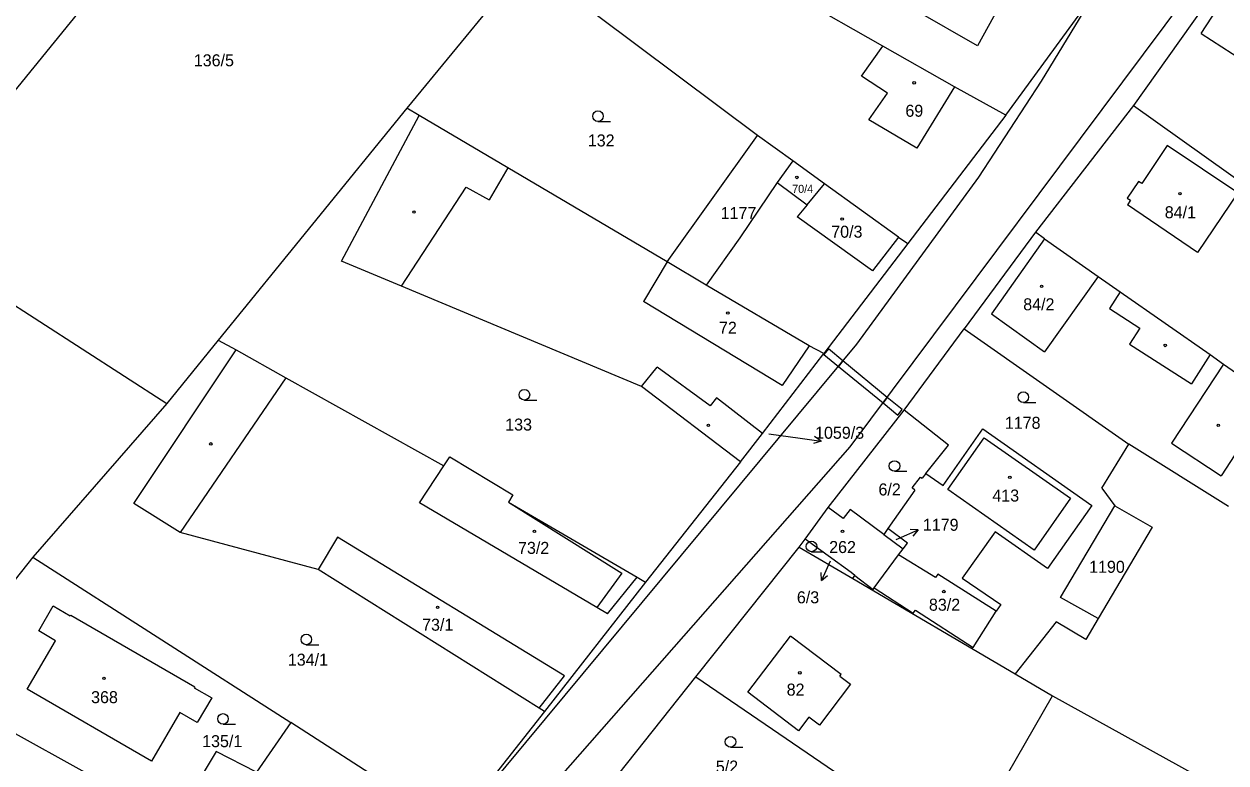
# Model space of a CAD drawing. Extents: x -694609 to -690140, y -1033292 to -1029794.
# Drawn here: x -692609.2 to -692438.9, y -1031810 to -1031705.3 of the extents above; entities that cross this region are included whole.
import ezdxf
from ezdxf.enums import TextEntityAlignment as Align

# ---------------------------------------------------------------- set-up
doc = ezdxf.new("R2010")
doc.units = 0
doc.header["$LTSCALE"] = 0.68
for name, color, linetype, lineweight in [('1', 7, 'Continuous', 25), ('13', 7, 'Continuous', 13), ('3', 7, 'Continuous', 25), ('4', 7, 'Continuous', 13), ('5', 7, 'Continuous', 25), ('7', 7, 'Continuous', 13)]:
    doc.layers.add(name, color=color, linetype=linetype, lineweight=lineweight)
doc.layers.add('2', color=7, linetype='Continuous')

msp = doc.modelspace()

# ---------------------------------------------------------------- linework, layer by layer
at = {"layer": '1'}
for p, q in [((-692593.96, -1031694.43), (-692626.76, -1031734.71)), ((-692467.92, -1031697.25), (-692474.09, -1031708.43)), ((-692487.5, -1031708.49), (-692503.62, -1031699.3)), ((-692492.12, -1031765.22), (-692442.05, -1031698.19)), ((-692470.09, -1031718.27), (-692457.55, -1031701.11)), ((-692465.03, -1031713.42), (-692457.55, -1031701.11)), ((-692505.25, -1031721.15), (-692527.93, -1031704.17)), ((-692474.09, -1031708.43), (-692482.82, -1031703.44)), ((-692477.36, -1031714.26), (-692487.5, -1031708.49)), ((-692470.09, -1031718.27), (-692477.36, -1031714.26)), ((-692473.9, -1031727.05), (-692465.03, -1031713.42)), ((-692554.95, -1031717.27), (-692581.65, -1031750.09)), ((-692564.18, -1031738.94), (-692553.18, -1031718.31)), ((-692553.18, -1031718.31), (-692554.95, -1031717.27)), ((-692540.63, -1031725.72), (-692553.18, -1031718.31)), ((-692470.09, -1031718.27), (-692483.96, -1031736.43)), ((-692451.98, -1031716.89), (-692425.76, -1031735.6)), ((-692518.08, -1031739.03), (-692505.25, -1031721.15)), ((-692500.28, -1031724.73), (-692505.25, -1031721.15)), ((-692495.76, -1031727.98), (-692500.28, -1031724.73)), ((-692518.08, -1031739.03), (-692540.63, -1031725.72)), ((-692502.48, -1031727.77), (-692507.78, -1031735.6)), ((-692498.22, -1031730.94), (-692495.76, -1031727.98)), ((-692485.27, -1031735.52), (-692495.76, -1031727.98)), ((-692491.21, -1031750.69), (-692473.9, -1031727.05)), ((-692626.76, -1031734.71), (-692588.96, -1031759.08)), ((-692465.89, -1031734.84), (-692475.97, -1031748.51)), ((-692464.62, -1031735.78), (-692465.89, -1031734.84)), ((-692507.78, -1031735.6), (-692512.52, -1031742.31)), ((-692483.96, -1031736.43), (-692495.85, -1031752)), ((-692485.27, -1031735.52), (-692483.96, -1031736.43)), ((-692464.62, -1031735.78), (-692456.99, -1031741.08)), ((-692555.71, -1031742.48), (-692564.18, -1031738.94)), ((-692512.52, -1031742.31), (-692518.08, -1031739.03)), ((-692456.99, -1031741.08), (-692453.87, -1031743.26)), ((-692521.7, -1031756.69), (-692555.71, -1031742.48)), ((-692497.95, -1031750.91), (-692512.52, -1031742.31)), ((-692453.87, -1031743.26), (-692441.12, -1031752.15)), ((-692484.5, -1031760.01), (-692475.97, -1031748.51)), ((-692475.97, -1031748.51), (-692452.67, -1031764.84)), ((-692581.65, -1031750.09), (-692588.96, -1031759.08)), ((-692581.65, -1031750.09), (-692579.14, -1031751.46)), ((-692559.98, -1031833.38), (-692491.21, -1031750.69)), ((-692504.56, -1031763.33), (-692495.85, -1031752)), ((-692495.85, -1031752), (-692497.95, -1031750.91)), ((-692441.12, -1031752.15), (-692439.26, -1031753.5)), ((-692439.26, -1031753.5), (-692432.4, -1031758.29)), ((-692572.07, -1031755.43), (-692549.71, -1031767.89)), ((-692507.66, -1031767.36), (-692521.7, -1031756.69)), ((-692588.96, -1031759.08), (-692607.91, -1031780.86)), ((-692495.25, -1031773.83), (-692484.5, -1031760.01)), ((-692478.23, -1031765), (-692484.5, -1031760.01)), ((-692507.66, -1031767.36), (-692504.56, -1031763.33)), ((-692478.94, -1031770.67), (-692473.35, -1031762.69)), ((-692551.82, -1031833.09), (-692492.12, -1031765.22)), ((-692481.4, -1031768.97), (-692478.23, -1031765)), ((-692456.48, -1031771.07), (-692452.67, -1031764.84)), ((-692438.54, -1031773.68), (-692452.67, -1031764.84)), ((-692549.71, -1031767.89), (-692548.84, -1031766.64)), ((-692548.84, -1031766.64), (-692539.91, -1031772)), ((-692507.66, -1031767.36), (-692521.11, -1031784.39)), ((-692553.16, -1031773.15), (-692549.71, -1031767.89)), ((-692481.4, -1031768.97), (-692481.95, -1031769.67)), ((-692481.4, -1031768.97), (-692478.94, -1031770.67)), ((-692483.36, -1031771), (-692482.17, -1031769.51)), ((-692482.96, -1031771.33), (-692483.36, -1031771)), ((-692482.17, -1031769.51), (-692481.95, -1031769.67)), ((-692456.48, -1031771.07), (-692454.65, -1031773.57)), ((-692539.91, -1031772), (-692540.55, -1031773.03)), ((-692482.96, -1031771.33), (-692486.8, -1031776.8)), ((-692587.05, -1031777.35), (-692593.64, -1031773.23)), ((-692528.04, -1031787.96), (-692553.16, -1031773.15)), ((-692540.55, -1031773.03), (-692522.33, -1031783.67)), ((-692498.49, -1031778.28), (-692495.25, -1031773.83)), ((-692493.12, -1031775.38), (-692495.25, -1031773.83)), ((-692492.13, -1031774.07), (-692493.12, -1031775.38)), ((-692487.38, -1031777.62), (-692492.13, -1031774.07)), ((-692462.36, -1031786.55), (-692454.65, -1031773.57)), ((-692454.65, -1031773.57), (-692449.36, -1031776.6)), ((-692567.5, -1031782.59), (-692587.05, -1031777.35)), ((-692486.8, -1031776.8), (-692487.38, -1031777.62)), ((-692487.38, -1031777.62), (-692484.64, -1031779.66)), ((-692484.01, -1031778.88), (-692486.8, -1031776.8)), ((-692471.61, -1031777.23), (-692476.25, -1031783.83)), ((-692464.17, -1031782.44), (-692471.61, -1031777.23)), ((-692449.36, -1031776.6), (-692456.99, -1031789.54)), ((-692514, -1031797.79), (-692499.34, -1031779.43)), ((-692499.34, -1031779.43), (-692498.49, -1031778.28)), ((-692499.34, -1031779.43), (-692491.77, -1031783.87)), ((-692491.98, -1031783.02), (-692498.49, -1031778.28)), ((-692484.64, -1031779.66), (-692484.01, -1031778.88)), ((-692607.91, -1031780.86), (-692622.58, -1031799.12)), ((-692607.91, -1031780.86), (-692571.38, -1031804.26)), ((-692488.72, -1031785.18), (-692485.27, -1031780.51)), ((-692485.27, -1031780.51), (-692484.64, -1031779.66)), ((-692480.04, -1031783.73), (-692485.27, -1031780.51)), ((-692536.22, -1031802.22), (-692567.5, -1031782.59)), ((-692491.46, -1031783.42), (-692491.98, -1031783.02)), ((-692526.5, -1031788.86), (-692522.33, -1031783.67)), ((-692522.33, -1031783.67), (-692521.11, -1031784.39)), ((-692491.77, -1031783.87), (-692491.46, -1031783.42)), ((-692491.77, -1031783.87), (-692468.74, -1031797.35)), ((-692491.46, -1031783.42), (-692488.89, -1031785.4)), ((-692479.71, -1031783.27), (-692480.04, -1031783.73)), ((-692471.46, -1031788.47), (-692479.71, -1031783.27)), ((-692476.25, -1031783.83), (-692470.78, -1031787.52)), ((-692488.89, -1031785.4), (-692488.72, -1031785.18)), ((-692488.72, -1031785.18), (-692483.21, -1031788.75)), ((-692607.08, -1031791.29), (-692605.05, -1031787.72)), ((-692605.05, -1031787.72), (-692602.65, -1031789.15)), ((-692526.5, -1031788.86), (-692528.04, -1031787.96)), ((-692470.78, -1031787.52), (-692471.46, -1031788.47)), ((-692456.99, -1031789.54), (-692462.36, -1031786.55)), ((-692602.65, -1031789.15), (-692602.56, -1031789.04)), ((-692602.56, -1031789.04), (-692585, -1031799.21)), ((-692483.21, -1031788.75), (-692482.87, -1031788.36)), ((-692482.87, -1031788.36), (-692474.72, -1031793.62)), ((-692474.72, -1031793.62), (-692471.46, -1031788.47)), ((-692456.99, -1031789.54), (-692458.73, -1031792.5)), ((-692604.74, -1031792.69), (-692607.08, -1031791.29)), ((-692462.95, -1031790.01), (-692468.74, -1031797.35)), ((-692458.73, -1031792.5), (-692462.95, -1031790.01)), ((-692608.73, -1031799.52), (-692604.74, -1031792.69)), ((-692524.91, -1031811.52), (-692514, -1031797.79)), ((-692514, -1031797.79), (-692494.36, -1031811.2)), ((-692468.74, -1031797.35), (-692463.48, -1031800.46)), ((-692598.83, -1031812.27), (-692622.58, -1031799.12)), ((-692591.13, -1031809.74), (-692608.73, -1031799.52)), ((-692585, -1031799.21), (-692585.07, -1031799.34)), ((-692585.07, -1031799.34), (-692582.59, -1031800.76)), ((-692582.59, -1031800.76), (-692584.63, -1031804.25)), ((-692477.55, -1031824.98), (-692463.48, -1031800.46)), ((-692463.48, -1031800.46), (-692416.83, -1031826.23)), ((-692587.11, -1031802.82), (-692591.13, -1031809.74)), ((-692584.63, -1031804.25), (-692587.11, -1031802.82)), ((-692535.46, -1031802.7), (-692548.33, -1031819.07)), ((-692548.33, -1031819.07), (-692571.38, -1031804.26)), ((-692581.95, -1031808.36), (-692585.34, -1031814))]:
    msp.add_line(p, q, dxfattribs=at)
for points in [[(-692533.41, -1031691.28), (-692535.83, -1031694), (-692554.95, -1031717.27)], [(-692440.5, -1031700.65), (-692451.98, -1031716.89), (-692465.89, -1031734.84)], [(-692500.28, -1031724.73), (-692502.48, -1031727.77), (-692498.22, -1031730.94)], [(-692593.64, -1031773.23), (-692579.14, -1031751.46), (-692572.07, -1031755.43)], [(-692473.35, -1031762.69), (-692457.92, -1031773.51), (-692464.17, -1031782.44)], [(-692521.11, -1031784.39), (-692535.46, -1031802.7), (-692536.22, -1031802.22)], [(-692571.38, -1031804.26), (-692576.24, -1031811.29), (-692581.95, -1031808.36)]]:
    msp.add_lwpolyline(points, dxfattribs=at)
at = {"layer": '13'}
for points in [[(-692495.85, -1031752.15), (-692493.81, -1031753.82), (-692493.17, -1031753.05), (-692495.23, -1031751.36)], [(-692493.17, -1031753.05), (-692493.81, -1031753.82), (-692487.48, -1031759.01), (-692486.88, -1031758.21)], [(-692487.48, -1031759.01), (-692485.4, -1031760.72), (-692484.77, -1031759.95), (-692486.88, -1031758.21)]]:
    msp.add_lwpolyline(points, close=True, dxfattribs=at)
at = {"layer": '3'}
for p, q in [((-692527.863, -1031719.14), (-692526.113, -1031719.14)), ((-692538.293, -1031758.59), (-692536.543, -1031758.59)), ((-692467.603, -1031758.93), (-692465.853, -1031758.93)), ((-692485.853, -1031768.68), (-692484.103, -1031768.68)), ((-692497.613, -1031780.07), (-692495.863, -1031780.07)), ((-692569.183, -1031793.24), (-692567.433, -1031793.24)), ((-692580.983, -1031804.49), (-692579.233, -1031804.49)), ((-692509.093, -1031807.74), (-692507.343, -1031807.74))]:
    msp.add_line(p, q, dxfattribs=at)
for centre in [(-692527.8629, -1031718.3898), (-692538.2929, -1031757.8398), (-692467.6029, -1031758.1798), (-692485.8529, -1031767.9298), (-692497.6129, -1031779.3198), (-692569.1829, -1031792.4898), (-692580.9829, -1031803.7398), (-692509.0929, -1031806.9898)]:
    msp.add_circle(centre, 0.75, dxfattribs=at)
at = {"layer": '4'}
for p, q in [((-692442.42, -1031706.71), (-692439.38, -1031702.08)), ((-692442.42, -1031706.71), (-692423.59, -1031718.8)), ((-692477.36, -1031714.26), (-692482.7, -1031722.91)), ((-692482.7, -1031722.91), (-692489.51, -1031718.93)), ((-692447.21, -1031722.56), (-692450.83, -1031727.94)), ((-692437.23, -1031729.27), (-692447.21, -1031722.56)), ((-692540.63, -1031725.72), (-692543.26, -1031730.22)), ((-692450.83, -1031727.94), (-692451.28, -1031727.63)), ((-692437.23, -1031729.27), (-692442.92, -1031737.68)), ((-692498.22, -1031730.94), (-692499.66, -1031732.67)), ((-692452.42, -1031730.3), (-692452.86, -1031730.95)), ((-692442.92, -1031737.68), (-692452.86, -1031730.95)), ((-692488.96, -1031740.31), (-692499.66, -1031732.67)), ((-692485.27, -1031735.52), (-692488.96, -1031740.31)), ((-692464.62, -1031735.78), (-692472.11, -1031746.4)), ((-692518.08, -1031739.03), (-692521.44, -1031744.65)), ((-692456.99, -1031741.08), (-692464.61, -1031751.75)), ((-692501.76, -1031756.52), (-692521.44, -1031744.65)), ((-692472.11, -1031746.4), (-692464.61, -1031751.75)), ((-692452.56, -1031750.68), (-692443.78, -1031756.31)), ((-692497.95, -1031750.91), (-692501.76, -1031756.52)), ((-692441.12, -1031752.15), (-692443.78, -1031756.31)), ((-692521.7, -1031756.69), (-692519.46, -1031753.95)), ((-692511.99, -1031759.39), (-692519.46, -1031753.95)), ((-692439.26, -1031753.5), (-692446.61, -1031764.71)), ((-692572.07, -1031755.43), (-692587.05, -1031777.35)), ((-692511.07, -1031758.3), (-692511.99, -1031759.39)), ((-692504.56, -1031763.33), (-692511.07, -1031758.3)), ((-692432.4, -1031758.29), (-692439.6, -1031769.3)), ((-692478.31, -1031771.26), (-692473.17, -1031763.93)), ((-692473.17, -1031763.93), (-692460.94, -1031772.48)), ((-692446.61, -1031764.71), (-692439.6, -1031769.3)), ((-692466.08, -1031779.84), (-692478.31, -1031771.26)), ((-692460.94, -1031772.48), (-692466.08, -1031779.84)), ((-692540.55, -1031773.03), (-692524.48, -1031783.12)), ((-692524.48, -1031783.12), (-692528.04, -1031787.96)), ((-692506.64, -1031799.98), (-692500.61, -1031792.01)), ((-692536.22, -1031802.22), (-692532.61, -1031797.65)), ((-692493.61, -1031797.67), (-692492.1, -1031798.82)), ((-692499.46, -1031805.41), (-692506.64, -1031799.98)), ((-692492.1, -1031798.82), (-692496.5, -1031804.64)), ((-692498.01, -1031803.5), (-692499.46, -1031805.41)), ((-692496.5, -1031804.64), (-692498.01, -1031803.5))]:
    msp.add_line(p, q, dxfattribs=at)
for points in [[(-692489.51, -1031718.93), (-692486.86, -1031715.15), (-692490.51, -1031712.73), (-692487.5, -1031708.49)], [(-692555.71, -1031742.48), (-692546.55, -1031728.46), (-692543.26, -1031730.22)], [(-692451.28, -1031727.63), (-692452.88, -1031729.99), (-692452.42, -1031730.3)], [(-692453.87, -1031743.26), (-692455.4, -1031745.64), (-692451.1, -1031748.4), (-692452.56, -1031750.68)], [(-692532.61, -1031797.65), (-692564.77, -1031778.02), (-692567.5, -1031782.59)], [(-692493.61, -1031797.67), (-692493.43, -1031797.44), (-692500.61, -1031792.01)]]:
    msp.add_lwpolyline(points, dxfattribs=at)
at = {"layer": '5'}
for centre in [(-692483.0668, -1031713.6692), (-692499.6868, -1031727.0692), (-692445.4168, -1031729.3792), (-692553.9368, -1031731.9692), (-692493.2768, -1031732.9592), (-692465.0168, -1031742.4792), (-692509.4668, -1031746.2692), (-692447.5068, -1031750.8592), (-692512.2268, -1031762.1692), (-692439.9868, -1031762.1792), (-692582.7168, -1031764.7992), (-692469.5168, -1031769.5292), (-692536.8668, -1031777.1792), (-692493.2268, -1031777.1892), (-692478.8668, -1031785.7092), (-692550.5768, -1031787.9492), (-692597.8568, -1031798.0092), (-692499.2668, -1031797.2192)]:
    msp.add_circle(centre, 0.175, dxfattribs=at)
at = {"layer": '7'}
for p, q in [((-692496.268, -1031764.398), (-692497.19, -1031763.762)), ((-692482.528, -1031776.979), (-692483.647, -1031776.929)), ((-692496.211, -1031784.132), (-692495.346, -1031783.42))]:
    msp.add_line(p, q, dxfattribs=at)
for points in [[(-692503.65, -1031763.36), (-692499.24, -1031763.98), (-692496.268, -1031764.398), (-692497.33, -1031764.754)], [(-692485.6, -1031778.35), (-692485.27, -1031778.2), (-692482.528, -1031776.979), (-692483.24, -1031777.844)], [(-692494.99, -1031781.39), (-692496.211, -1031784.132), (-692496.261, -1031783.013)]]:
    msp.add_lwpolyline(points, dxfattribs=at)

# ---------------------------------------------------------------- texts
at = {"layer": '2'}
for s, height, p in [('136/5', 1.7, (-692582.28, -1031711.335)), ('69', 1.7, (-692483.049, -1031718.475)), ('132', 1.7, (-692527.409, -1031722.685)), ('70/4', 1.139, (-692498.869, -1031729.254)), ('1177', 1.7, (-692507.96, -1031732.965)), ('84/1', 1.7, (-692445.359, -1031732.845)), ('70/3', 1.7, (-692492.609, -1031735.605)), ('84/2', 1.7, (-692465.409, -1031745.885)), ('72', 1.7, (-692509.459, -1031749.205)), ('133', 1.7, (-692539.109, -1031762.915)), ('1178', 1.7, (-692467.7, -1031762.665)), ('6/2', 1.7, (-692486.55, -1031772.095)), ('413', 1.7, (-692470.099, -1031772.965)), ('73/2', 1.7, (-692536.979, -1031780.375)), ('262', 1.7, (-692493.219, -1031780.255)), ('1190', 1.7, (-692455.76, -1031783.055)), ('83/2', 1.7, (-692478.769, -1031788.425)), ('73/1', 1.7, (-692550.569, -1031791.255)), ('134/1', 1.7, (-692568.96, -1031796.205)), ('368', 1.7, (-692597.779, -1031801.515)), ('82', 1.7, (-692499.869, -1031800.445)), ('135/1', 1.7, (-692581.1, -1031807.745)), ('5/2', 1.7, (-692509.59, -1031811.345))]:
    msp.add_text(s, height=height, dxfattribs=at).set_placement(p, align=Align.CENTER)
for s, p in [('1059/3', (-692497.11, -1031764.075)), ('1179', (-692481.84, -1031777.105))]:
    msp.add_text(s, height=1.7, dxfattribs=at).set_placement(p)
msp.add_text('6/3', height=1.7, dxfattribs=at).set_placement((-692496.529, -1031787.375), align=Align.RIGHT)

doc.saveas('drawing.dxf')
